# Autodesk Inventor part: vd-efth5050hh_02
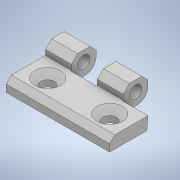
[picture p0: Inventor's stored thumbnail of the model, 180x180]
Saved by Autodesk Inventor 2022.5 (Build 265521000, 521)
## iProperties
Created: 2019-12
Part Number: vd-efth5050hh_02
Material: 一般
Document SubType Name: Modeling
Designer: ImaoCorp
Density: 1 g/cm^3
Appearance: 既定
Author: ImaoCorp
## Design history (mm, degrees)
feature "vd-efth5050hh_02"
node "ソリッド1"
